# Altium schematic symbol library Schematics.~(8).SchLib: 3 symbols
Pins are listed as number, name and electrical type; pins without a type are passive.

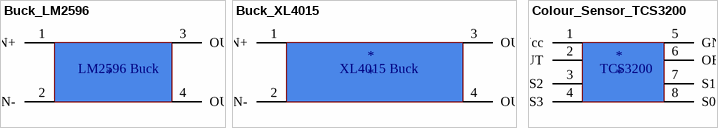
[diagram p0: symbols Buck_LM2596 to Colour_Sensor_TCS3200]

## Buck_LM2596
designator ?
footprint Model Name (Footprint not found)
footprint Buck_LM2596
pins: 1 IN+ (power), 2 IN- (power), 3 OUT+ (power), 4 OUT- (power)

## Buck_XL4015
designator *
footprint Buck_LM4015
pins: 1 IN+ (power), 2 IN- (power), 3 OUT+ (power), 4 OUT- (power)

## Colour_Sensor_TCS3200
designator *
pins: 1 Vcc (power), 2 OUT, 3 S2, 4 S3, 5 GND (power), 6 OE, 7 S1, 8 S0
